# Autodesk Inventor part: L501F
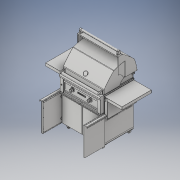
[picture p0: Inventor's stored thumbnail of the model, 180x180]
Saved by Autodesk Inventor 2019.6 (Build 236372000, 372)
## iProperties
Created: 2025-04
Part Number: L501F
Material: Generic
Description: CATIA V5 STEP
Document SubType Name: Modeling
Designer: MMAK
Authority: none
Density: 1 g/cm^3
Appearance: Default
Company: none
Title: C:\Users\MMAK\Documents\SmarTeam\WEBSITE CAD\SEDONA\2025 SEDONA\L501F.stp
Author: none
Revision Number: ANY
Sending System: CATIA V5 STEP AP203 v2
Preprocessor: CATIA Unofficial Packaging Version SP2
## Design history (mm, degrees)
feature "81798-1_81723-1_81722-1_38022-1-solid1"
feature "81798-1_81723-1_81722-1_32769-1-solid1"
feature "81798-1_81723-1_81722-1_32769-2-solid1"
feature "81798-1_81723-1_81722-1_32218-1-solid1"
feature "81798-1_81723-1_81722-1_32218-2-solid1"
feature "81798-1_81723-1_81534-2_37528-2-solid1"
feature "81798-1_81723-1_81534-2_32769-1-solid1"
feature "81798-1_81723-1_81534-2_32769-2-solid1"
feature "81798-1_81723-1_81534-2_32218-14-solid1"
feature "81798-1_81723-1_81534-2_37165-1-solid1"
feature "81798-1_81723-1_81676-2_37886-1-solid1"
feature "81798-1_81723-1_81676-2_32769-1-solid1"
feature "81798-1_81723-1_81676-2_32769-2-solid1"
feature "81798-1_81723-1_81676-2_37165-11-solid1"
feature "81798-1_81723-1_81721-1_38021-1-solid1"
feature "81798-1_81723-1_81721-1_38025-1-solid1"
feature "81798-1_81723-1_81721-1_32769-1-solid1"
feature "81798-1_81723-1_81721-1_32769-2-solid1"
feature "81798-1_81723-1_81721-1_32769-3-solid1"
feature "81798-1_81723-1_81721-1_32769-4-solid1"
feature "81798-1_81723-1_81721-1_32769-5-solid1"
feature "81798-1_81723-1_81721-1_32769-6-solid1"
feature "81798-1_81723-1_81721-1_32769-7-solid1"
feature "81798-1_81723-1_81721-1_32769-8-solid1"
feature "81798-1_81723-1_81721-1_32769-9-solid1"
feature "81798-1_81723-1_81721-1_32769-10-solid1"
feature "81798-1_81723-1_81721-1_32769-11-solid1"
feature "81798-1_81723-1_81721-1_32769-12-solid1"
feature "81798-1_81723-1_81721-1_32769-21-solid1"
feature "81798-1_81723-1_81721-1_32769-25-solid1"
feature "81798-1_81723-1_81721-1_32769-26-solid1"
feature "81798-1_81723-1_81721-1_32769-27-solid1"
feature "81798-1_81723-1_30662-1-solid1"
feature "81798-1_81723-1_30662-1-solid2"
feature "81798-1_81723-1_30662-1-solid3"
feature "81798-1_81723-1_33843-1-solid1"
feature "81798-1_81723-1_33843-1-solid2"
feature "81798-1_81723-1_33843-2-solid1"
feature "81798-1_81723-1_33843-2-solid2"
feature "81798-1_81723-1_37167-1-solid1"
feature "81798-1_81723-1_37167-17-solid1"
feature "81798-1_81723-1_37167-18-solid1"
feature "81798-1_81723-1_37167-19-solid1"
feature "81798-1_81723-1_37167-21-solid1"
feature "81798-1_81723-1_37167-24-solid1"
feature "81798-1_81723-1_37167-26-solid1"
feature "81798-1_81723-1_37167-28-solid1"
feature "81798-1_81723-1_37167-30-solid1"
feature "81798-1_81723-1_37167-32-solid1"
feature "81798-1_81723-1_37167-34-solid1"
feature "81798-1_81723-1_37167-36-solid1"
feature "81798-1_81723-1_37167-38-solid1"
feature "81798-1_81723-1_37167-40-solid1"
feature "81798-1_81723-1_37167-42-solid1"
feature "81798-1_81723-1_37167-44-solid1"
feature "81798-1_81723-1_30662-2-solid1"
feature "81798-1_81723-1_30662-2-solid2"
feature "81798-1_81723-1_30662-2-solid3"
feature "81798-1_81404-3_37070-1-solid1"
feature "81798-1_81404-3_32769-1-solid1"
feature "81798-1_81404-3_32769-2-solid1"
feature "81798-1_81404-3_32769-4-solid1"
feature "81798-1_81404-3_32769-6-solid1"
feature "81798-1_38026-1-solid1"
feature "81798-1_37168-1-solid1"
feature "81798-1_37168-4-solid1"
feature "81798-1_70696-2_37100-1-solid1"
feature "81798-1_70696-2_34888-1-solid1"
feature "81798-1_70696-2_31643-1-solid1"
feature "81798-1_70696-2_31643-3-solid1"
feature "81798-1_70696-1_37100-1-solid1"
feature "81798-1_70696-1_34888-1-solid1"
feature "81798-1_70696-1_31643-1-solid1"
feature "81798-1_70696-1_31643-3-solid1"
feature "81798-1_70696-3_37100-1-solid1"
feature "81798-1_70696-3_31643-2-solid1"
feature "81798-1_70696-3_34888-3-solid1"
feature "81798-1_70696-3_31643-4-solid1"
feature "81798-1_70696-4_37100-1-solid1"
feature "81798-1_70696-4_31643-2-solid1"
feature "81798-1_70696-4_34888-3-solid1"
feature "81798-1_70696-4_31643-4-solid1"
feature "81798-1_31876-10-solid1"
feature "81798-1_31876-1-solid1"
feature "81798-1_31876-2-solid1"
feature "81798-1_31876-5-solid1"
feature "81798-1_31876-11-solid1"
feature "81798-1_31876-12-solid1"
feature "81798-1_37167-47-solid1"
feature "81798-1_37167-45-solid1"
feature "81798-1_37167-48-solid1"
feature "81798-1_37167-46-solid1"
feature "81798-1_37167-41-solid1"
feature "81798-1_37167-43-solid1"
feature "81798-1_37167-49-solid1"
feature "81798-1_37167-50-solid1"
feature "81798-1_37165-3-solid1"
feature "81798-1_37165-2-solid1"
feature "81798-1_30292-1-solid1"
feature "81798-1_30292-2-solid1"
feature "81798-1_30292-4-solid1"
feature "81798-1_30292-6-solid1"
feature "81798-1_81530-1_37102-1-solid1"
feature "81798-1_81530-1_31205-1-solid1"
feature "81798-1_81530-1_31206-5-solid1"
feature "81798-1_81530-1_31206-6-solid1"
feature "81798-1_81530-1_31206-4-solid1"
feature "81798-1_81530-1_31206-7-solid1"
feature "81798-1_37166-2-solid1"
feature "81798-1_37166-1-solid1"
feature "81798-1_37166-3-solid1"
feature "81798-1_37166-4-solid1"
feature "81798-1_37166-6-solid1"
feature "81798-1_37166-10-solid1"
feature "81798-1_37166-12-solid1"
feature "81798-1_37166-15-solid1"
feature "81798-1_37795-1-solid1"
feature "81798-1_37795-2-solid1"
feature "81798-1_81788-1_81792-1_37540-1-solid1"
feature "81798-1_81788-1_81792-1_37797-1-solid1"
feature "81798-1_81788-1_81792-1_38153-1-solid1"
feature "81798-1_81788-1_81792-1_30292-1-solid1"
feature "81798-1_81788-1_81792-1_30292-2-solid1"
feature "81798-1_81788-1_81792-1_30292-3-solid1"
feature "81798-1_81788-1_81792-1_30292-5-solid1"
feature "81798-1_81788-1_81792-1_30292-6-solid1"
feature "81798-1_81788-1_81792-1_30292-7-solid1"
feature "81798-1_81788-1_81792-1_30292-8-solid1"
feature "81798-1_81788-1_81792-1_30292-9-solid1"
feature "81798-1_81788-1_81792-1_30292-10-solid1"
feature "81798-1_81788-1_81792-1_30292-11-solid1"
feature "81798-1_81788-1_81792-1_30292-12-solid1"
feature "81798-1_81788-1_81792-1_30292-13-solid1"
feature "81798-1_81788-1_81792-1_30292-14-solid1"
feature "81798-1_81788-1_81792-1_30292-16-solid1"
feature "81798-1_81788-1_81792-1_30292-18-solid1"
feature "81798-1_81788-1_81792-1_30292-20-solid1"
feature "81798-1_81788-1_81792-1_30292-22-solid1"
feature "81798-1_81788-1_32218-1-solid1"
feature "81798-1_81788-1_32218-2-solid1"
feature "81798-1_81788-1_32218-3-solid1"
feature "81798-1_81788-1_32218-4-solid1"
feature "81798-1_81788-1_37166-1-solid1"
feature "81798-1_81788-1_37166-2-solid1"
feature "81798-1_81788-1_37166-3-solid1"
feature "81798-1_81788-1_37166-4-solid1"
feature "81798-1_81788-1_35792-1-solid1"
feature "81798-1_81788-1_35792-2-solid1"
feature "81798-1_81788-1_35624-1-solid1"
feature "81798-1_81788-1_35624-1-solid2"
feature "81798-1_81788-1_35624-1-solid3"
feature "81798-1_81788-1_35624-1-solid4"
feature "81798-1_81788-1_35624-1-solid5"
feature "81798-1_81788-1_35624-2-solid1"
feature "81798-1_81788-1_35624-2-solid2"
feature "81798-1_81788-1_35624-2-solid3"
feature "81798-1_81788-1_35624-2-solid4"
feature "81798-1_81788-1_35624-2-solid5"
feature "81798-1_81789-1_81793-1_37540-1-solid1"
feature "81798-1_81789-1_81793-1_37549-1-solid1"
feature "81798-1_81789-1_81793-1_38153-1-solid1"
feature "81798-1_81789-1_81793-1_30292-1-solid1"
feature "81798-1_81789-1_81793-1_30292-2-solid1"
feature "81798-1_81789-1_81793-1_30292-3-solid1"
feature "81798-1_81789-1_81793-1_30292-4-solid1"
feature "81798-1_81789-1_81793-1_30292-5-solid1"
feature "81798-1_81789-1_81793-1_30292-6-solid1"
feature "81798-1_81789-1_81793-1_30292-7-solid1"
feature "81798-1_81789-1_81793-1_30292-8-solid1"
feature "81798-1_81789-1_81793-1_30292-9-solid1"
feature "81798-1_81789-1_81793-1_30292-10-solid1"
feature "81798-1_81789-1_81793-1_30292-11-solid1"
feature "81798-1_81789-1_81793-1_30292-12-solid1"
feature "81798-1_81789-1_81793-1_30292-13-solid1"
feature "81798-1_81789-1_81793-1_30292-15-solid1"
feature "81798-1_81789-1_81793-1_30292-17-solid1"
feature "81798-1_81789-1_81793-1_30292-19-solid1"
feature "81798-1_81789-1_81793-1_30292-21-solid1"
feature "L501-2_80624-1_33752-1-solid1"
feature "L501-2_80624-1_33752-1-solid2"
feature "L501-2_80624-1_33752-1-solid3"
feature "L501-2_80624-1_33753-1-solid1"
feature "L501-2_80624-1_33754-1-solid1"
feature "L501-2_80624-1_14011-25-solid1"
feature "L501-2_80624-1_14011-27-solid1"
feature "L501-2_80624-1_14011-29-solid1"
feature "L501-2_80624-1_14011-30-solid1"
feature "L501-2_80624-1_14011-32-solid1"
feature "L501-2_80624-1_14011-34-solid1"
feature "L501-2_80624-1_30616-53-solid1"
feature "L501-2_80624-1_30292-1-solid1"
feature "L501-2_80624-1_30292-3-solid1"
feature "L501-2_80624-1_31643-25-solid1"
feature "L501-2_80624-1_31643-27-solid1"
feature "L501-2_80624-1_30616-29-solid1"
feature "L501-2_80624-1_30616-31-solid1"
feature "L501-2_80624-1_30616-44-solid1"
feature "L501-2_80624-1_30616-46-solid1"
feature "L501-2_80624-1_30616-52-solid1"
feature "L501-2_80624-1_14034-1-solid1"
feature "L501-2_80624-1_14034-3-solid1"
feature "L501-2_80624-1_33758-1-solid1"
feature "L501-2_80624-1_33759-1-solid1"
feature "L501-2_80624-1_30616-49-solid1"
feature "L501-2_80624-1_30616-51-solid1"
feature "L501-2_80624-1_33755-1-solid1"
feature "L501-2_80624-1_14034-4-solid1"
feature "L501-2_80624-1_14034-5-solid1"
feature "L501-2_80624-1_14011-35-solid1"
feature "L501-2_80624-1_14011-36-solid1"
feature "L501-2_80624-1_14011-38-solid1"
feature "L501-2_80624-1_14011-40-solid1"
feature "L501-2_80624-1_14011-42-solid1"
feature "L501-2_80624-1_14011-44-solid1"
feature "L501-2_80624-1_14011-46-solid1"
feature "L501-2_80624-1_14011-48-solid1"
feature "L501-2_80624-1_14011-51-solid1"
feature "L501-2_80624-1_14011-53-solid1"
feature "L501-2_80624-1_14011-55-solid1"
feature "L501-2_80624-1_14011-57-solid1"
feature "L501-2_80624-1_14011-59-solid1"
feature "L501-2_80624-1_14011-60-solid1"
feature "L501-2_80624-1_14011-63-solid1"
feature "L501-2_80624-1_14011-64-solid1"
feature "L501-2_80624-1_32620-1-solid1"
feature "L501-2_80624-1_32620-2-solid1"
feature "L501-2_80624-1_32620-3-solid1"
feature "L501-2_80624-1_32620-4-solid1"
feature "L501-2_80624-1_32620-5-solid1"
feature "L501-2_81796-1_70832-1_L18041-1-solid1"
feature "L501-2_81796-1_70832-1_33763-1-solid1"
feature "L501-2_81796-1_70832-1_37975-1-solid1"
feature "L501-2_81796-1_32218-1-solid1"
feature "L501-2_81796-1_32218-2-solid1"
feature "L501-2_70834-1_33765-2-solid1"
feature "L501-2_70834-1_33767-1-solid1"
feature "L501-2_70834-1_33768-1-solid1"
feature "L501-2_70834-2_33765-2-solid1"
feature "L501-2_70834-2_33767-1-solid1"
feature "L501-2_70834-2_33768-1-solid1"
feature "L501-2_81718-1_70838-1_38011-1-solid1"
feature "L501-2_81718-1_70838-1_14011-1-solid1"
feature "L501-2_81718-1_81628-1_37837-2-solid1"
feature "L501-2_81718-1_81628-1_32218-3-solid1"
feature "L501-2_81718-1_81628-1_32218-4-solid1"
feature "L501-2_81718-1_81628-1_31782-1-solid1"
feature "L501-2_81718-1_81628-1_32769-1-solid1"
feature "L501-2_81718-1_81628-1_32769-2-solid1"
feature "L501-2_81718-1_81628-1_32769-3-solid1"
feature "L501-2_81718-1_81628-1_32769-4-solid1"
feature "L501-2_81718-1_81627-1_37834-2-solid1"
feature "L501-2_81718-1_81627-1_32769-1-solid1"
feature "L501-2_81718-1_81627-1_32769-2-solid1"
feature "L501-2_81718-1_81627-1_32769-3-solid1"
feature "L501-2_81718-1_81627-1_32769-4-solid1"
feature "L501-2_81718-1_81627-1_32769-5-solid1"
feature "L501-2_81718-1_81627-1_31782-1-solid1"
feature "L501-2_81718-1_81627-1_32218-3-solid1"
feature "L501-2_81718-1_81627-1_32218-4-solid1"
feature "L501-2_81718-1_37845-1-solid1"
feature "L501-2_81718-1_37846-1-solid1"
feature "L501-2_81718-1_32470-1-solid1"
feature "L501-2_81718-1_32470-2-solid1"
feature "L501-2_81718-1_14012-1-solid1"
feature "L501-2_81718-1_14012-2-solid1"
feature "L501-2_81718-1_14012-4-solid1"
feature "L501-2_81718-1_14012-6-solid1"
feature "L501-2_81718-1_14012-8-solid1"
feature "L501-2_81718-1_14012-10-solid1"
feature "L501-2_81718-1_14012-12-solid1"
feature "L501-2_81718-1_14012-14-solid1"
feature "L501-2_81718-1_14014-1-solid1"
feature "L501-2_81718-1_14014-2-solid1"
feature "L501-2_81718-1_14014-3-solid1"
feature "L501-2_81718-1_14014-4-solid1"
feature "L501-2_38162-1-solid1"
feature "L501-2_L20016-1-solid1"
feature "L501-2_L20016-2-solid1"
feature "L501-2_L20016-3-solid1"
feature "L501-2_L20016-4-solid1"
feature "L501-2_11117-1-solid1"
feature "L501-2_11117-2-solid1"
feature "L501-2_11117-3-solid1"
feature "L501-2_11117-4-solid1"
feature "L501-2_34200-1-solid1"
feature "L501-2_34200-2-solid1"
feature "L501-2_10001-1-solid1"
feature "L501-2_10001-2-solid1"
feature "L501-2_80732-1_80636-1_33780-1-solid1"
feature "L501-2_80732-1_80636-1_L10041-1-solid1"
feature "L501-2_80732-1_80636-1_L10041-2-solid1"
feature "NONE"
feature "L501-2_80732-1_13024-1-solid1"
feature "NONE:1"
feature "L501-2_80732-1_13024-2-solid1"
feature "L501-2_80732-1_34267-1-solid1"
feature "L501-2_80732-1_34268-1-solid1"
feature "L501-2_80732-1_13029-1-solid1"
feature "L501-2_31773-1-solid1"
feature "L501-2_31773-2-solid1"
feature "L501-2_34106-1-solid1"
feature "L501-2_33558-1-solid1"
feature "L501-2_81630-1_32106-1-solid1"
feature "L501-2_81630-1_Part2^81630-1-solid1"
feature "L501-2_81630-1_Part2^81630-1-solid2"
feature "L501-2_38155-1-solid1"
feature "L501-2_38156-1-solid1"
feature "L501-2_30417-1-solid1"
feature "L501-2_14013-1-solid1"
feature "L501-2_14013-2-solid1"
feature "L501-2_36967-1-solid1"
feature "L501-2_36967-2-solid1"
feature "L501-2_31930-1-solid1"
feature "L501-2_31930-2-solid1"
feature "L501-2_31930-3-solid1"
feature "L501-2_31930-4-solid1"
feature "L501-2_31930-5-solid1"
feature "L501-2_31930-6-solid1"
feature "L501-2_31930-7-solid1"
feature "L501-2_31930-8-solid1"
feature "L501-2_31930-9-solid1"
feature "L501-2_31930-10-solid1"
feature "L501-2_31317-1-solid1"
feature "L501-2_31317-2-solid1"
feature "L501-2_31317-3-solid1"
feature "L501-2_31317-4-solid1"
feature "L501-2_31317-5-solid1"
feature "L501-2_31317-6-solid1"
feature "L501-2_14012-1-solid1"
feature "L501-2_14012-2-solid1"
feature "L501-2_14012-3-solid1"
feature "L501-2_14012-4-solid1"
feature "L501-2_32554-1-solid1"
feature "L501-2_32554-1-solid2"
feature "L501-2_32554-2-solid1"
feature "L501-2_32554-2-solid2"
feature "37795-1-solid1"
feature "37795-2-solid1"
feature "81789-1_81793-1_37540-1-solid1"
feature "81789-1_81793-1_37549-1-solid1"
feature "81789-1_81793-1_38153-1-solid1"
feature "81789-1_81793-1_30292-1-solid1"
feature "81789-1_81793-1_30292-2-solid1"
feature "81789-1_81793-1_30292-3-solid1"
feature "81789-1_81793-1_30292-4-solid1"
feature "81789-1_81793-1_30292-5-solid1"
feature "81789-1_81793-1_30292-6-solid1"
feature "81789-1_81793-1_30292-7-solid1"
feature "81789-1_81793-1_30292-8-solid1"
feature "81789-1_81793-1_30292-9-solid1"
feature "81789-1_81793-1_30292-10-solid1"
feature "81789-1_81793-1_30292-11-solid1"
feature "81789-1_81793-1_30292-12-solid1"
feature "81789-1_81793-1_30292-13-solid1"
feature "81789-1_81793-1_30292-15-solid1"
feature "81789-1_81793-1_30292-17-solid1"
feature "81789-1_81793-1_30292-19-solid1"
feature "81789-1_81793-1_30292-21-solid1"
feature "81792-1_37540-1-solid1"
feature "81792-1_37797-1-solid1"
feature "81792-1_38153-1-solid1"
feature "81792-1_30292-1-solid1"
feature "81792-1_30292-2-solid1"
feature "81792-1_30292-3-solid1"
feature "81792-1_30292-5-solid1"
feature "81792-1_30292-6-solid1"
feature "81792-1_30292-7-solid1"
feature "81792-1_30292-8-solid1"
feature "81792-1_30292-9-solid1"
feature "81792-1_30292-10-solid1"
feature "81792-1_30292-11-solid1"
feature "81792-1_30292-12-solid1"
feature "81792-1_30292-13-solid1"
feature "81792-1_30292-14-solid1"
feature "81792-1_30292-16-solid1"
feature "81792-1_30292-18-solid1"
feature "81792-1_30292-20-solid1"
feature "81792-1_30292-22-solid1"
body "Solid1"
body "Solid2"
body "Solid3"
body "Solid4"
body "Solid5"
body "Solid6"
body "Solid7"
body "Solid8"
body "Solid9"
body "Solid10"
body "Solid11"
body "Solid12"
body "Solid13"
body "Solid14"
body "Solid15"
body "Solid16"
body "Solid17"
body "Solid18"
body "Solid19"
body "Solid20"
body "Solid21"
body "Solid22"
body "Solid23"
body "Solid24"
body "Solid25"
body "Solid26"
body "Solid27"
body "Solid28"
body "Solid29"
body "Solid30"
body "Solid31"
body "Solid32"
body "Solid33"
body "Solid34"
body "Solid35"
body "Solid36"
body "Solid37"
body "Solid38"
body "Solid39"
body "Solid40"
body "Solid41"
body "Solid42"
body "Solid43"
body "Solid44"
body "Solid45"
body "Solid46"
body "Solid47"
body "Solid48"
body "Solid49"
body "Solid50"
body "Solid51"
body "Solid52"
body "Solid53"
body "Solid54"
body "Solid55"
body "Solid56"
body "Solid57"
body "Solid58"
body "Solid59"
body "Solid60"
body "Solid61"
body "Solid62"
body "Solid63"
body "Solid64"
body "Solid65"
body "Solid66"
body "Solid67"
body "Solid68"
body "Solid69"
body "Solid70"
body "Solid71"
body "Solid72"
body "Solid73"
body "Solid74"
body "Solid75"
body "Solid76"
body "Solid77"
body "Solid78"
body "Solid79"
body "Solid80"
body "Solid81"
body "Solid82"
body "Solid83"
body "Solid84"
body "Solid85"
body "Solid86"
body "Solid87"
body "Solid88"
body "Solid89"
body "Solid90"
body "Solid91"
body "Solid92"
body "Solid93"
body "Solid94"
body "Solid95"
body "Solid96"
body "Solid97"
body "Solid98"
body "Solid99"
body "Solid100"
body "Solid101"
body "Solid102"
body "Solid103"
body "Solid104"
body "Solid105"
body "Solid106"
body "Solid107"
body "Solid108"
body "Solid109"
body "Solid110"
body "Solid111"
body "Solid112"
body "Solid113"
body "Solid114"
body "Solid115"
body "Solid116"
body "Solid117"
body "Solid118"
body "Solid119"
body "Solid120"
body "Solid121"
body "Solid122"
body "Solid123"
body "Solid124"
body "Solid125"
body "Solid126"
body "Solid127"
body "Solid128"
body "Solid129"
body "Solid130"
body "Solid131"
body "Solid132"
body "Solid133"
body "Solid134"
body "Solid135"
body "Solid136"
body "Solid137"
body "Solid138"
body "Solid139"
body "Solid140"
body "Solid141"
body "Solid142"
body "Solid143"
body "Solid144"
body "Solid145"
body "Solid146"
body "Solid147"
body "Solid148"
body "Solid149"
body "Solid150"
body "Solid151"
body "Solid152"
body "Solid153"
body "Solid154"
body "Solid155"
body "Solid156"
body "Solid157"
body "Solid158"
body "Solid159"
body "Solid160"
body "Solid161"
body "Solid162"
body "Solid163"
body "Solid164"
body "Solid165"
body "Solid166"
body "Solid167"
body "Solid168"
body "Solid169"
body "Solid170"
body "Solid171"
body "Solid172"
body "Solid173"
body "Solid174"
body "Solid175"
body "Solid176"
body "Solid177"
body "Solid178"
body "Solid179"
body "Solid180"
body "Solid181"
body "Solid182"
body "Solid183"
body "Solid184"
body "Solid185"
body "Solid186"
body "Solid187"
body "Solid188"
body "Solid189"
body "Solid190"
body "Solid191"
body "Solid192"
body "Solid193"
body "Solid194"
body "Solid195"
body "Solid196"
body "Solid197"
body "Solid198"
body "Solid199"
body "Solid200"
body "Solid201"
body "Solid202"
body "Solid203"
body "Solid204"
body "Solid205"
body "Solid206"
body "Solid207"
body "Solid208"
body "Solid209"
body "Solid210"
body "Solid211"
body "Solid212"
body "Solid213"
body "Solid214"
body "Solid215"
body "Solid216"
body "Solid217"
body "Solid218"
body "Solid219"
body "Solid220"
body "Solid221"
body "Solid222"
body "Solid223"
body "Solid224"
body "Solid225"
body "Solid226"
body "Solid227"
body "Solid228"
body "Solid229"
body "Solid230"
body "Solid231"
body "Solid232"
body "Solid233"
body "Solid234"
body "Solid235"
body "Solid236"
body "Solid237"
body "Solid238"
body "Solid239"
body "Solid240"
body "Solid241"
body "Solid242"
body "Solid243"
body "Solid244"
body "Solid245"
body "Solid246"
body "Solid247"
body "Solid248"
body "Solid249"
body "Solid250"
body "Solid251"
body "Solid252"
body "Solid253"
body "Solid254"
body "Solid255"
body "Solid256"
body "Solid257"
body "Solid258"
body "Solid259"
body "Solid260"
body "Solid261"
body "Solid262"
body "Solid263"
body "Solid264"
body "Solid265"
body "Solid266"
body "Solid267"
body "Solid268"
body "Solid269"
body "Solid270"
body "Solid271"
body "Solid272"
body "Solid273"
body "Solid274"
body "Solid275"
body "Solid276"
body "Solid277"
body "Solid278"
body "Solid279"
body "Solid280"
body "Solid281"
body "Solid282"
body "Solid283"
body "Solid284"
body "Solid285"
body "Solid286"
body "Solid287"
body "Solid288"
body "Solid289"
body "Solid290"
body "Solid291"
body "Solid292"
body "Solid293"
body "Solid294"
body "Solid295"
body "Solid296"
body "Solid297"
body "Solid298"
body "Solid299"
body "Solid300"
body "Solid301"
body "Solid302"
body "Solid303"
body "Solid304"
body "Solid305"
body "Solid306"
body "Solid307"
body "Solid308"
body "Solid309"
body "Solid310"
body "Solid311"
body "Solid312"
body "Solid313"
body "Solid314"
body "Solid315"
body "Solid316"
body "Solid317"
body "Solid318"
body "Solid319"
body "Solid320"
body "Solid321"
body "Solid322"
body "Solid323"
body "Solid324"
body "Solid325"
body "Solid326"
body "Solid327"
body "Solid328"
body "Solid329"
body "Solid330"
body "Solid331"
body "Solid332"
body "Solid333"
body "Solid334"
body "Solid335"
body "Solid336"
body "Solid337"
body "Solid338"
body "Solid339"
body "Solid340"
body "Solid341"
body "Solid342"
body "Solid343"
body "Solid344"
body "Solid345"
body "Solid346"
body "Solid347"
body "Solid348"
body "Solid349"
body "Solid350"
body "Solid351"
body "Solid352"
body "Solid353"
body "Solid354"
body "Solid355"
body "Solid356"
body "Solid357"
body "Solid358"
body "Solid359"
body "Solid360"
body "Solid361"
body "Solid362"
body "Solid363"
body "Solid364"
body "Solid365"
body "Solid366"
body "Solid367"
body "Solid368"
body "Solid369"
body "Solid370"
body "Solid371"
body "Solid372"
body "Solid373"
body "Solid374"
body "Solid375"
body "Solid376"
body "Solid377"
body "Solid378"
body "Solid379"
body "Solid380"
body "Solid381"
body "Solid382"
body "Solid383"
body "Solid384"
body "Solid385"
body "Solid386"
body "Solid387"
body "Solid388"
body "Solid389"
body "Solid390"
